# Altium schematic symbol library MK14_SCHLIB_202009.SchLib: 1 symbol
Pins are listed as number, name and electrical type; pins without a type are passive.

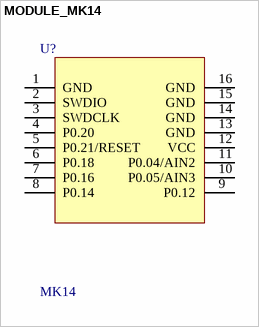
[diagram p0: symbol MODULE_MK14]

## MODULE_MK14
designator U?, comment MK14
footprint MK14_202009 (12.1*8.9mm)
pins: 1 GND, 2 SWDIO, 3 SWDCLK, 4 P0.20, 5 P0.21/RESET, 6 P0.18, 7 P0.16, 8 P0.14, 9 P0.12, 10 P0.05/AIN3, 11 P0.04/AIN2, 12 VCC, 13 GND, 14 GND, 15 GND, 16 GND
